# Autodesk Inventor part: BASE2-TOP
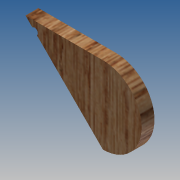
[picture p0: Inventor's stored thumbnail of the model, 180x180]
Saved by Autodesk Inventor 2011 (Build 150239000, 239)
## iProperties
Created: 2011-01
Part Number: BASE2-TOP
Document SubType Name: Modeling
Designer: Microsoft
Density: 1 g/cm^3
Author: Microsoft
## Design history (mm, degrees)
sketch "Sketch1"
  geometry: L1 (9.525, 0)-(9.525, 19.05); L2 (-9.525, 19.05)-(-9.525, 0); L3 (-9.525, 19.05)-(9.525, 0); A1 r 9.525 centre (0, 0) between (-9.525, 0) and (9.525, 0); A2 r 9.525 centre (0, 19.05) between (9.525, 19.05) and (-9.525, 19.05); 1 further point
  constraints: 6 end point, 4 point on circle, 3 tangent, 2 centre point, 1 coincident, 1 vertical alignment
  dimensions: "d3" = 9.525 radius of A2; "d4" = 9.525 radius of A1; "d5" = 19.05 distance of L1.start L1.end; "d6" = 19.05 distance of point (0, 0) A2.centre
extrude "Extrusion1" new body sketch "Sketch1" distance "d7" = 12.7; taper "d8" = 0 deg
sketch "Sketch2"
  geometry: L1 (13.47, 0)-(13.47, 12.7) reference; L2 (0, 0)-(26.941, 0) reference; C1 r 0.794 at (13.47, 6.35); 1 further point
  constraints: 1 centre point, 1 midpoint
  dimensions: "d31" = 1.5875 diameter of C1; "d32" = 6.35 distance from line of L2 C1.centre
extrude "Extrusion2" cut sketch "Sketch2" distance "d10" = 6.35; taper "d11" = 0 deg
sketch "Sketch3"
  geometry: C1 r 1.587 at (0, -3.175); C2 r 0.794 at (0, -3.175) reference; 1 further point
  constraints: 1 centre point, 1 concentric
  dimensions: "d12" = 3.175 diameter of C1
extrude "Extrusion3" cut sketch "Sketch3" distance "d13" = 1.5875; taper "d14" = 0 deg
workplane "Work Plane1"
sketch "Sketch5"
  geometry: L1 (-9.525, 19.05)-(-8.622, 19.953); L2 (9.525, 0)-(-9.525, 19.05) reference; C1 r 0.794 at (-7.28, 16.805); 1 further point
  constraints: 2 end point, 1 centre point, 1 perpendicular, 1 point on line
  dimensions: "d21" = 1.5875 diameter of C1; "d22" = 3.175 distance from line of L1 C1.centre
extrude "Extrusion4" cut sketch "Sketch5" distance "d23" = 3.175; taper "d24" = 0 deg
sketch "Sketch6"
  geometry: C1 r 1.588 at (-7.28, -16.805); A1 r 0.794 centre (-7.28, -16.805) between (-6.719, -16.244) and (-7.841, -17.366) reference; 1 further point
  constraints: 1 centre point, 1 coincident
  dimensions: "d25" = 3.175 diameter of C1
extrude "Extrusion5" cut sketch "Sketch6" distance "d26" = 1.5875; taper "d27" = 0 deg
fillet "Fillet1" dims "d30" = 2.54
sketch "Sketch8"
  geometry: L1 (-9.525, 19.05)-(9.525, 0) reference; L2 (-9.525, 0)-(-9.525, 19.05) reference; A1 r 9.525 centre (0, 0) between (-9.525, 0) and (9.525, 0) reference
extrude "Extrusion7" cut sketch "Sketch8" distance "d33" = 3.175; taper "d34" = 0 deg
sketch "Sketch9"
  geometry: L1 (7.841, -17.366)-(6.719, -16.244) reference; C1 r 1.588 at (7.28, -16.805); A1 r 0.794 centre (7.28, -16.805) between (6.719, -16.244) and (7.841, -17.366) reference; 1 further point
  constraints: 1 centre point, 1 coincident
  dimensions: "d37" = 3.175 diameter of C1
extrude "Extrusion8" cut sketch "Sketch9" distance "d35" = 0.79375; taper "d36" = 0 deg
sketch "Sketch10"
  geometry: L1 (-6.719, 16.244)-(9.525, 0) reference; L2 (-9.525, 19.05)-(-7.841, 17.366) reference; L3 (-9.525, 0)-(-9.525, 19.05) reference; A1 r 0.794 centre (-7.28, 16.805) between (-7.841, 17.366) and (-6.719, 16.244) reference; A2 r 9.525 centre (0, 0) between (-9.525, 0) and (9.525, 0) reference
extrude "Extrusion9" sketch "Sketch10" distance "d38" = 3.175; taper "d39" = 0 deg
mirror "Mirror1"
body "Solid1"
other parameters: "d17" = -6.35
